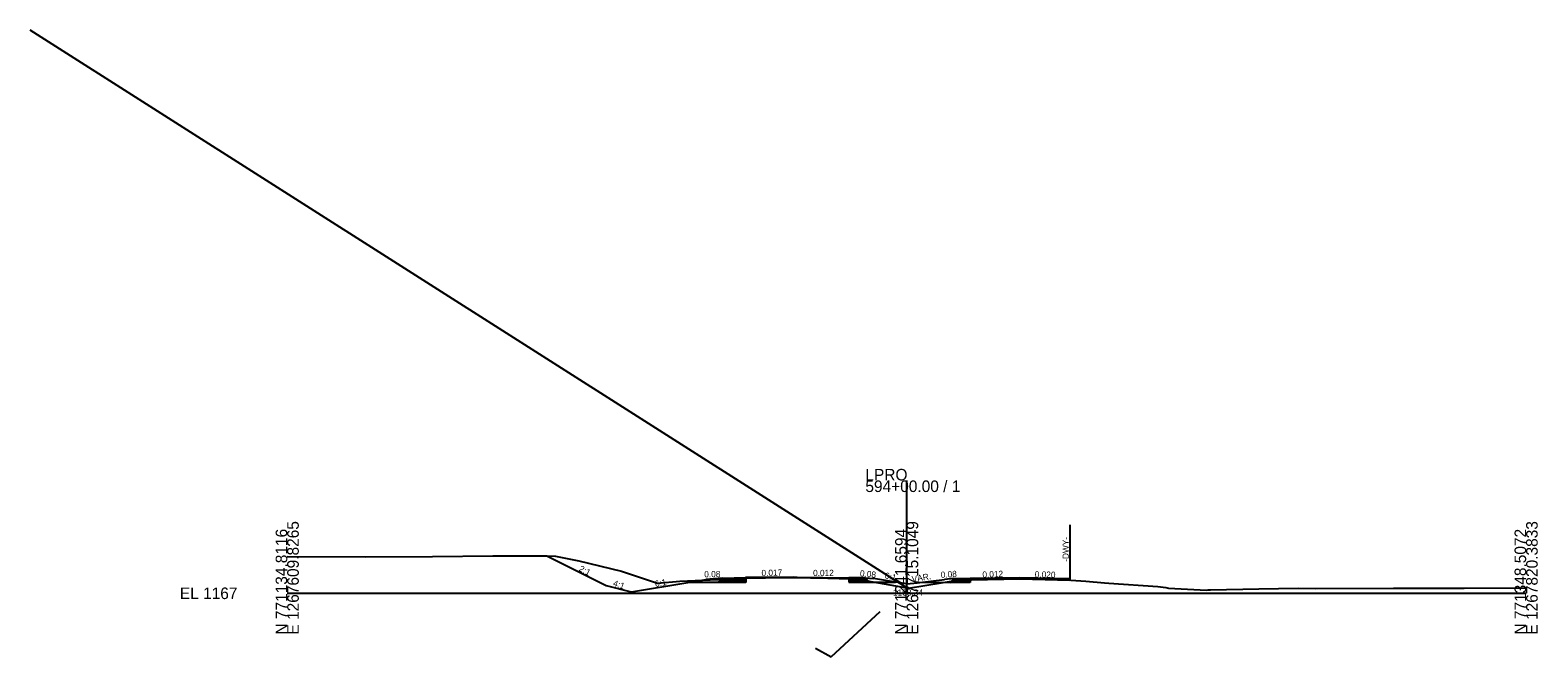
# Model space of a CAD drawing. Extents: x -3833 to 1267678, y -522 to 773248.
# Drawn here: x -62.2 to 302.8, y 4984.6 to 5136.4 of the extents above; entities that cross this region are included whole.
import ezdxf

# ---------------------------------------------------------------- set-up
doc = ezdxf.new("R2010")
doc.units = 0
for name, color, linetype in [('Exist Cross Section Cell', 7, 'Continuous'), ('Exist XS Center Line Elevation Label', 7, 'Continuous'), ('Exist XS Ground Line', 7, 'Continuous'), ('Prop CMT DNC', 7, 'Continuous'), ('Prop CMT Pvmt Course 1', 7, 'Continuous'), ('Prop CMT Shld Paved Course 1', 7, 'Continuous'), ('Prop CMT Shld Paved Course 2', 7, 'Continuous'), ('Prop CMT Shld Paved Course 4', 7, 'Continuous'), ('Prop CMT Slope Grass', 7, 'Continuous'), ('Prop CMT Subgrade Earthwork', 7, 'Continuous'), ('Prop Corridor Mesh Bottom', 7, 'Continuous'), ('Prop XS Ditch Slope Text', 7, 'Continuous'), ('Prop XS Finish Grade', 7, 'Continuous'), ('Prop XS SE Text', 7, 'Continuous'), ('Prop XS Shear Point Element', 7, 'Continuous'), ('Prop XS Shear Point Label', 7, 'Continuous'), ('Scratch_Level_1', 7, 'Continuous'), ('Scratch_Level_5', 7, 'Continuous')]:
    doc.layers.add(name, color=color, linetype=linetype)

msp = doc.modelspace()

# ---------------------------------------------------------------- linework, layer by layer
at = {"layer": 'Exist Cross Section Cell'}
for p, q in [((150, 5000), (150, 5027.33)), ((0, 5000), (150, 5000)), ((150, 5000), (300, 5000))]:
    msp.add_line(p, q, dxfattribs=at)
at = {"layer": 'Exist XS Ground Line'}
for p, q in [((35.21, 5008.94), (49.79, 5009.11)), ((49.79, 5009.11), (62.84, 5009.08)), ((62.84, 5009.08), (64.96, 5009.01)), ((0, 5008.89), (18.94, 5008.85)), ((18.94, 5008.85), (35.21, 5008.94)), ((64.96, 5009.01), (70.63, 5007.87)), ((64.96, 5009.01), (70.63, 5007.87)), ((70.63, 5007.87), (80.93, 5005.4)), ((70.63, 5007.87), (80.93, 5005.4)), ((80.93, 5005.4), (89.68, 5002.48)), ((80.93, 5005.4), (89.68, 5002.48)), ((89.68, 5002.48), (95.08, 5002.93)), ((89.68, 5002.48), (95.08, 5002.93)), ((95.08, 5002.93), (106.12, 5003.41)), ((95.08, 5002.93), (106.12, 5003.41)), ((106.12, 5003.41), (109.03, 5003.6)), ((106.12, 5003.41), (109.03, 5003.6)), ((109.03, 5003.6), (111.13, 5003.73)), ((109.03, 5003.6), (111.13, 5003.73)), ((111.13, 5003.73), (115.82, 5003.77)), ((111.13, 5003.73), (115.82, 5003.77)), ((115.82, 5003.77), (122.49, 5003.82)), ((115.82, 5003.77), (122.49, 5003.82)), ((122.49, 5003.82), (130.88, 5003.63)), ((122.49, 5003.82), (130.88, 5003.63)), ((130.88, 5003.63), (136.39, 5003.5)), ((130.88, 5003.63), (136.39, 5003.5)), ((136.39, 5003.5), (137.28, 5003.45)), ((136.39, 5003.5), (137.28, 5003.45)), ((137.28, 5003.45), (138.61, 5003.39)), ((137.28, 5003.45), (138.61, 5003.39)), ((138.61, 5003.39), (139.13, 5003.27)), ((138.61, 5003.39), (139.13, 5003.27)), ((139.13, 5003.27), (141.77, 5002.81)), ((139.13, 5003.27), (141.77, 5002.81)), ((141.77, 5002.81), (150, 5001.34)), ((141.77, 5002.81), (150, 5001.34)), ((150.44, 5001.27), (158.32, 5002.55)), ((150.44, 5001.27), (158.32, 5002.55)), ((158.32, 5002.55), (160.79, 5002.94)), ((158.32, 5002.55), (160.79, 5002.94)), ((160.79, 5002.94), (161.22, 5003.03)), ((160.79, 5002.94), (161.22, 5003.03)), ((161.22, 5003.03), (161.6, 5003.11)), ((161.22, 5003.03), (161.6, 5003.11)), ((161.6, 5003.11), (164.75, 5003.25)), ((161.6, 5003.11), (164.75, 5003.25)), ((164.75, 5003.25), (165.69, 5003.3)), ((165.69, 5003.3), (174.93, 5003.49)), ((174.93, 5003.49), (177.41, 5003.54)), ((174.93, 5003.49), (177.41, 5003.54)), ((177.41, 5003.54), (182.15, 5003.41)), ((177.41, 5003.54), (182.15, 5003.41)), ((182.15, 5003.41), (189.74, 5003.19)), ((182.15, 5003.41), (189.74, 5003.19)), ((189.74, 5003.19), (192.19, 5003.01)), ((189.74, 5003.19), (192.19, 5003.01)), ((192.19, 5003.01), (193.37, 5002.92)), ((192.19, 5003.01), (193.37, 5002.92)), ((193.37, 5002.92), (197.89, 5002.51)), ((193.37, 5002.92), (197.89, 5002.51)), ((197.89, 5002.51), (198.92, 5002.45)), ((197.89, 5002.51), (198.92, 5002.45)), ((198.92, 5002.45), (210.8, 5001.65)), ((198.92, 5002.45), (210.8, 5001.65)), ((150, 5001.34), (150.44, 5001.27)), ((150, 5001.34), (150.44, 5001.27)), ((210.8, 5001.65), (212.73, 5001.41)), ((210.8, 5001.65), (212.73, 5001.41)), ((212.73, 5001.41), (213.38, 5001.24)), ((212.73, 5001.41), (213.38, 5001.24)), ((213.38, 5001.24), (222.61, 5000.78)), ((213.38, 5001.24), (222.61, 5000.78)), ((222.61, 5000.78), (222.99, 5000.82)), ((222.61, 5000.78), (222.99, 5000.82)), ((222.99, 5000.82), (223.6, 5000.83)), ((222.99, 5000.82), (223.6, 5000.83)), ((223.6, 5000.83), (235.29, 5001.07)), ((223.6, 5000.83), (235.29, 5001.07)), ((235.29, 5001.07), (244.78, 5001.21)), ((235.29, 5001.07), (244.78, 5001.21)), ((244.78, 5001.21), (249.09, 5001.2)), ((244.78, 5001.21), (249.09, 5001.2)), ((249.09, 5001.2), (267.85, 5001.25)), ((267.85, 5001.25), (283.29, 5001.23)), ((283.29, 5001.23), (285.02, 5001.23)), ((285.02, 5001.23), (300, 5001.31))]:
    msp.add_line(p, q, dxfattribs=at)
at = {"layer": 'Prop CMT Pvmt Course 1'}
for p, q in [((111.13, 5003.81), (111.01, 5003.8)), ((111.02, 5003.73), (111.02, 5003.8)), ((111.13, 5003.74), (111.02, 5003.73)), ((122.49, 5003.89), (111.13, 5003.81)), ((122.49, 5003.82), (111.13, 5003.74)), ((122.49, 5003.89), (123.5, 5003.88)), ((130.88, 5003.63), (122.49, 5003.82)), ((123.5, 5003.88), (135.97, 5003.75)), ((136.39, 5003.5), (130.88, 5003.63)), ((130.88, 5003.63), (136.39, 5003.5)), ((135.97, 5003.75), (135.97, 5003.51)), ((135.97, 5003.51), (136.39, 5003.5)), ((177.44, 5003.74), (165.39, 5003.62)), ((165.39, 5003.62), (165.39, 5003.62)), ((165.39, 5003.62), (165.39, 5003.37)), ((165.39, 5003.37), (165.39, 5003.37)), ((165.39, 5003.37), (165.39, 5003.28)), ((165.39, 5003.28), (165.69, 5003.3)), ((165.69, 5003.3), (177.42, 5003.54)), ((177.42, 5003.54), (177.49, 5003.54)), ((189.49, 5003.49), (177.44, 5003.74)), ((177.44, 5003.74), (177.44, 5003.74)), ((177.49, 5003.54), (177.52, 5003.54)), ((177.52, 5003.54), (189.49, 5003.2)), ((189.49, 5003.24), (189.49, 5003.49)), ((189.49, 5003.2), (189.49, 5003.24)), ((189.49, 5003.24), (189.49, 5003.24))]:
    msp.add_line(p, q, dxfattribs=at)
at = {"layer": 'Prop CMT Shld Paved Course 1'}
for p, q in [((105.1, 5003.42), (105.35, 5003.67)), ((111.02, 5003.43), (105.1, 5003.42)), ((105.1, 5003.42), (105.1, 5003.42)), ((105.1, 5003.42), (105.1, 5003.42)), ((105.35, 5003.67), (111.02, 5003.8)), ((105.35, 5003.67), (105.35, 5003.67)), ((111.02, 5003.8), (111.02, 5003.43)), ((111.02, 5003.43), (111.02, 5003.43)), ((139.97, 5003.76), (135.97, 5003.75)), ((135.97, 5003.75), (135.97, 5003.75)), ((135.97, 5003.75), (135.97, 5003.5)), ((135.97, 5003.5), (140.22, 5003.51)), ((135.97, 5003.5), (135.97, 5003.5)), ((135.97, 5003.5), (135.97, 5003.5)), ((140.22, 5003.51), (139.97, 5003.76)), ((139.97, 5003.76), (139.97, 5003.76)), ((161.17, 5003.32), (161.39, 5003.55)), ((165.39, 5003.37), (161.17, 5003.32)), ((161.39, 5003.55), (165.39, 5003.62)), ((165.39, 5003.62), (165.39, 5003.37)), ((189.49, 5003.49), (189.49, 5003.24))]:
    msp.add_line(p, q, dxfattribs=at)
at = {"layer": 'Prop CMT Shld Paved Course 2'}
for p, q in [((104.76, 5003.08), (105.1, 5003.42)), ((111.02, 5003.1), (104.76, 5003.08)), ((104.76, 5003.08), (104.76, 5003.08)), ((104.76, 5003.08), (104.76, 5003.08)), ((105.1, 5003.42), (111.02, 5003.43)), ((105.1, 5003.42), (105.1, 5003.42)), ((111.02, 5003.43), (111.02, 5003.1)), ((111.02, 5003.1), (111.02, 5003.1)), ((140.22, 5003.51), (135.97, 5003.5)), ((135.97, 5003.5), (135.97, 5003.5)), ((135.97, 5003.5), (135.97, 5003.16)), ((135.97, 5003.16), (140.55, 5003.18)), ((135.97, 5003.16), (135.97, 5003.16)), ((135.97, 5003.16), (135.97, 5003.16)), ((140.55, 5003.18), (140.22, 5003.51)), ((140.22, 5003.51), (140.22, 5003.51)), ((160.92, 5003.04), (161.17, 5003.32)), ((165.39, 5003.04), (160.92, 5003.04)), ((161.17, 5003.32), (165.39, 5003.37)), ((165.39, 5003.37), (165.39, 5003.04))]:
    msp.add_line(p, q, dxfattribs=at)
at = {"layer": 'Prop CMT Shld Paved Course 4'}
for p, q in [((104.31, 5002.62), (104.76, 5003.08)), ((111.02, 5002.64), (104.31, 5002.62)), ((104.76, 5003.08), (105.26, 5003.09)), ((105.26, 5003.09), (111.02, 5003.1)), ((111.02, 5003.1), (111.02, 5002.64)), ((140.05, 5003.17), (135.97, 5003.16)), ((135.97, 5003.16), (135.97, 5003.16)), ((135.97, 5003.16), (135.97, 5002.71)), ((135.97, 5002.71), (141.01, 5002.72)), ((135.97, 5002.71), (135.97, 5002.71)), ((135.97, 5002.71), (135.97, 5002.71)), ((140.55, 5003.18), (140.05, 5003.17)), ((140.05, 5003.17), (140.05, 5003.17)), ((141.01, 5002.72), (140.55, 5003.18)), ((140.55, 5003.18), (140.55, 5003.18)), ((160.43, 5002.57), (160.92, 5003.04)), ((161.22, 5003.04), (161.31, 5003.04)), ((161.31, 5003.04), (165.39, 5003.04)), ((165.39, 5003.04), (165.39, 5002.58))]:
    msp.add_line(p, q, dxfattribs=at)
at = {"layer": 'Prop CMT Slope Grass'}
for p, q in [((97.01, 5002.62), (101.35, 5003.35)), ((105.35, 5003.67), (101.35, 5003.35)), ((139.97, 5003.76), (141.97, 5003.6)), ((147.31, 5002.71), (141.97, 5003.6)), ((152.58, 5002.57), (159.17, 5003.35)), ((161.39, 5003.55), (159.17, 5003.35))]:
    msp.add_line(p, q, dxfattribs=at)
at = {"layer": 'Prop CMT Subgrade Earthwork'}
for p, q in [((111.02, 5002.64), (97.01, 5002.62)), ((111.02, 5003.73), (111.02, 5002.64)), ((135.97, 5003.51), (135.97, 5002.71)), ((135.97, 5002.71), (147.31, 5002.71)), ((165.39, 5002.58), (152.58, 5002.57)), ((165.39, 5003.28), (165.39, 5002.58))]:
    msp.add_line(p, q, dxfattribs=at)
at = {"layer": 'Prop Corridor Mesh Bottom'}
for p, q in [((111.02, 5003.68), (111.02, 5003.43)), ((135.97, 5003.75), (135.97, 5003.5)), ((165.39, 5003.62), (165.39, 5003.37)), ((189.49, 5003.49), (189.49, 5003.24))]:
    msp.add_line(p, q, dxfattribs=at)
at = {"layer": 'Prop XS Finish Grade'}
for p, q in [((62.84, 5009.08), (77.25, 5001.85)), ((77.25, 5001.85), (77.25, 5001.85)), ((77.25, 5001.85), (77.25, 5001.85)), ((77.25, 5001.85), (83.25, 5000.35)), ((83.35, 5000.35), (97.01, 5002.62)), ((141.97, 5003.6), (141.97, 5003.6)), ((150, 5002.26), (147.31, 5002.71)), ((150, 5002.26), (152.58, 5002.57)), ((83.25, 5000.35), (83.25, 5000.35)), ((83.25, 5000.35), (83.3, 5000.35)), ((83.3, 5000.35), (83.3, 5000.35)), ((83.3, 5000.35), (83.35, 5000.35)), ((83.35, 5000.35), (83.35, 5000.35))]:
    msp.add_line(p, q, dxfattribs=at)
at = {"layer": 'Prop XS Shear Point Element'}
msp.add_line((189.49, 5016.56), (189.49, 5003.49), dxfattribs=at)
at = {"layer": 'Scratch_Level_1'}
msp.add_line((150, 5001.34), (-62.25, 5136.4), dxfattribs=at)
at = {"layer": 'Scratch_Level_5'}
for p, q in [((131.72, 4984.61), (143.58, 4995.63)), ((127.93, 4986.71), (131.72, 4984.61))]:
    msp.add_line(p, q, dxfattribs=at)

# ---------------------------------------------------------------- texts
at = {"layer": 'Exist Cross Section Cell'}
for s, p in [('594+00.00 / 1', (140, 5024.53)), ('LPRO', (140, 5027.33)), ('EL 1167', (-26, 4998.6))]:
    msp.add_text(s, height=2.8, dxfattribs=at).set_placement(p)
for s, p in [('E 1267609.8265', (2.8, 4990)), ('E 1267715.1049', (152.8, 4990)), ('E 1267820.3833', (302.8, 4990)), ('N 771134.8116', (0, 4990)), ('N 771241.6594', (150, 4990)), ('N 771348.5072', (300, 4990))]:
    msp.add_text(s, height=2.8, rotation=90, dxfattribs=at).set_placement(p)
at = {"layer": 'Exist XS Center Line Elevation Label'}
msp.add_text('1168.34', height=1.5, dxfattribs=at).set_placement((146.68, 4999.42))
at = {"layer": 'Prop CMT DNC'}
for p in [(62.78, 5009.08), (105.35, 5003.67), (111.02, 5003.68), (111.02, 5003.68), (123.5, 5003.88), (135.97, 5003.75), (135.97, 5003.75), (139.97, 5003.76), (141.97, 5003.6), (165.39, 5003.62), (165.39, 5003.62), (177.44, 5003.74), (189.49, 5003.49), (189.49, 5003.49), (83.3, 5000.35), (83.35, 5000.35), (219.84, 5000.92)]:
    msp.add_text('X', height=0.00025, dxfattribs=at).set_placement(p)
at = {"layer": 'Prop XS Ditch Slope Text'}
for s, rotation, p in [('2:1', 332.219, (70.5, 5005.5)), ('4:1', 341.4779, (78.77, 5001.84)), ('6:1', 10.2685, (89.16, 5001.52)), ('6:1', 346.8183, (144.58, 5003.65)), ('VAR.', 9.5559, (151.37, 5002.66))]:
    msp.add_text(s, height=1.5, rotation=rotation, dxfattribs=at).set_placement(p)
at = {"layer": 'Prop XS SE Text'}
for s, rotation, p in [('0.08', 1.397, (101, 5003.84)), ('0.017', 1.397, (114.86, 5004.16)), ('0.012', 0.2693, (127.34, 5004.17)), ('0.08', 354.0053, (138.62, 5004.14)), ('0.08', 3.7156, (158.29, 5003.72)), ('0.012', 2.3888, (168.37, 5003.77)), ('0.020', 358.8542, (181.01, 5003.84))]:
    msp.add_text(s, height=1.5, rotation=rotation, dxfattribs=at).set_placement(p)
at = {"layer": 'Prop XS Shear Point Label'}
msp.add_text('-DWY-', height=1.5, rotation=90, dxfattribs=at).set_placement((189.26, 5007.63))

doc.saveas('drawing.dxf')
